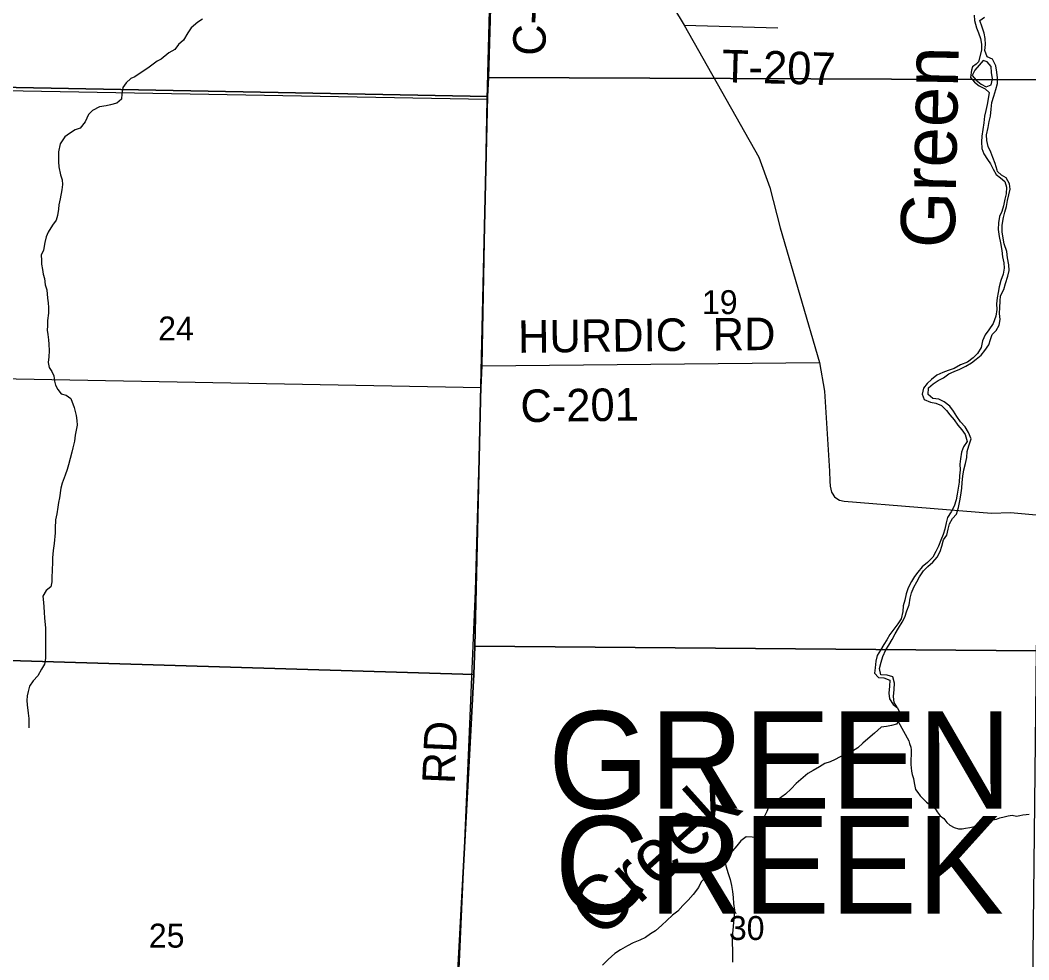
# Model space of a CAD drawing. Extents: x 0 to 34, y 0 to 22.
# Drawn here: x 25.169 to 26.932, y 15.382 to 17.024 of the extents above; entities that cross this region are included whole.
import ezdxf

# ---------------------------------------------------------------- set-up
doc = ezdxf.new("R2010")
doc.units = 0
for name, color, linetype in [('GM_X_County_Road', 7, 'Continuous'), ('GM_X_County_Road_Text', 7, 'Continuous'), ('GM_X_Minor_River', 7, 'Continuous'), ('GM_X_Minor_River_Text', 7, 'Continuous'), ('GM_X_Section', 7, 'Continuous'), ('GM_X_Section_Text', 7, 'Continuous'), ('GM_X_Township_Road', 7, 'Continuous'), ('GM_X_Township_Road_Text', 7, 'Continuous'), ('GM_X_Township_Text', 7, 'Continuous')]:
    doc.layers.add(name, color=color, linetype=linetype)

msp = doc.modelspace()

# ---------------------------------------------------------------- linework, layer by layer
at = {"layer": 'GM_X_County_Road'}
for p, q in [((25.9854, 16.8861), (26.0016, 17.5418)), ((25.9763, 16.4198), (25.9854, 16.8861)), ((25.9746, 16.3822), (25.9763, 16.4198)), ((25.9763, 16.4198), (26.566, 16.4258))]:
    msp.add_line(p, q, dxfattribs=at)
for points in [[(26.0883, 17.4156), (26.3294, 17.015), (26.4602, 16.7846), (26.4794, 16.7319), (26.4973, 16.6609), (26.566, 16.4258)], [(26.566, 16.4258), (26.5747, 16.3759), (26.5835, 16.236), (26.5843, 16.2185), (26.585, 16.2101), (26.5874, 16.1995), (26.5882, 16.1976), (26.5926, 16.191), (26.5963, 16.1882), (26.6013, 16.1852), (26.6092, 16.1839), (26.867, 16.1627), (26.9001, 16.1639), (26.9576, 16.1588)], [(24.007, 16.4066), (24.2617, 16.4112), (24.9115, 16.4019), (25.9746, 16.3822)], [(25.9196, 14.987), (25.9448, 15.5625), (25.9647, 16.0268), (25.9746, 16.3822)]]:
    msp.add_lwpolyline(points, dxfattribs=at)
at = {"layer": 'GM_X_Minor_River'}
for points in [[(26.8367, 17.0328), (26.8372, 17.0233), (26.8403, 17.0106), (26.8442, 17.0018), (26.8474, 16.9922), (26.8494, 16.9823), (26.8494, 16.9713), (26.844, 16.9513), (26.8397, 16.9473), (26.8335, 16.9425), (26.8318, 16.9368), (26.8299, 16.9236), (26.8369, 16.9158), (26.8455, 16.9095), (26.8556, 16.9043), (26.8626, 16.8976), (26.8612, 16.8863), (26.859, 16.8765), (26.8568, 16.8663), (26.8547, 16.8561), (26.8532, 16.8444), (26.8518, 16.833), (26.8499, 16.8213), (26.8493, 16.8114), (26.8497, 16.7997), (26.8536, 16.7904), (26.8598, 16.7804), (26.8653, 16.7727), (26.8696, 16.7634), (26.875, 16.7545), (26.8825, 16.7486)], [(25.4875, 17.026), (25.4798, 17.0204), (25.4679, 17.0103), (25.4621, 17.0016), (25.4548, 16.9892), (25.4456, 16.9813), (25.4394, 16.973), (25.4287, 16.9671), (25.4157, 16.9558), (25.4085, 16.9521), (25.3943, 16.9416), (25.3871, 16.9364), (25.3786, 16.9312), (25.3695, 16.9252), (25.3622, 16.9222), (25.3542, 16.9147), (25.3484, 16.9065), (25.3468, 16.8951), (25.3459, 16.886), (25.3378, 16.8792), (25.3272, 16.8759), (25.3192, 16.8745), (25.3078, 16.8723), (25.2956, 16.8664), (25.2887, 16.8593), (25.2829, 16.8464), (25.274, 16.8355), (25.2652, 16.8326), (25.2553, 16.8262), (25.2469, 16.8199), (25.2392, 16.8082), (25.236, 16.7938), (25.2358, 16.7767), (25.2368, 16.7676), (25.2397, 16.7535), (25.2426, 16.7451), (25.2433, 16.7368), (25.242, 16.7277), (25.2388, 16.7118), (25.2364, 16.7012), (25.236, 16.6936), (25.234, 16.683), (25.232, 16.6743), (25.2254, 16.666), (25.2181, 16.6539), (25.2142, 16.6456), (25.2122, 16.6354), (25.2097, 16.6221), (25.2059, 16.6134), (25.2061, 16.6047), (25.2064, 16.5975), (25.2082, 16.5884), (25.2093, 16.5804), (25.2115, 16.5728), (25.2128, 16.5617), (25.2154, 16.5526), (25.2168, 16.5385), (25.2182, 16.5302), (25.2188, 16.5218), (25.2184, 16.5123), (25.2171, 16.4991), (25.217, 16.4899), (25.2165, 16.4824), (25.2176, 16.4748), (25.2186, 16.4653), (25.2193, 16.4577), (25.2199, 16.4463), (25.219, 16.436), (25.2181, 16.4262), (25.2196, 16.4174), (25.2244, 16.4102), (25.2277, 16.4029), (25.2291, 16.3934), (25.2306, 16.3862), (25.2347, 16.3785), (25.2406, 16.3709), (25.2497, 16.3689), (25.2576, 16.3631), (25.2635, 16.3475), (25.2668, 16.3334), (25.2678, 16.3247), (25.2685, 16.3167), (25.2652, 16.2989), (25.264, 16.2883), (25.2608, 16.2769), (25.2592, 16.2693), (25.2537, 16.2474), (25.2513, 16.2387), (25.2474, 16.2288), (25.2423, 16.2152), (25.2403, 16.2061), (25.2378, 16.1895), (25.2362, 16.1811)], [(26.8768, 16.7621), (26.8733, 16.7736), (26.869, 16.7839), (26.8655, 16.7935), (26.8608, 16.8035), (26.8588, 16.8138), (26.858, 16.8237), (26.8609, 16.8362), (26.8627, 16.8468), (26.8649, 16.8562), (26.8664, 16.8687), (26.8674, 16.88), (26.8708, 16.891), (26.8745, 16.9026), (26.8774, 16.9132), (26.877, 16.9234), (26.8761, 16.9333), (26.8745, 16.944), (26.8684, 16.956), (26.859, 16.96), (26.8551, 16.9707), (26.8562, 16.9813), (26.8557, 16.992), (26.8537, 17.0015), (26.8502, 17.0119), (26.8463, 17.0234), (26.8544, 17.0292)], [(26.852, 16.9534), (26.8453, 16.9456), (26.8379, 16.9367), (26.8331, 16.9273), (26.8397, 16.9192), (26.849, 16.9121), (26.8572, 16.9073), (26.8664, 16.9108), (26.8686, 16.9214)], [(26.8686, 16.9214), (26.867, 16.9328), (26.8661, 16.9431), (26.8591, 16.9509), (26.852, 16.9534)], [(26.8825, 16.7486), (26.8899, 16.742), (26.893, 16.7324), (26.8923, 16.7207), (26.8898, 16.7112), (26.8876, 16.6999), (26.8847, 16.6897), (26.881, 16.6807), (26.8788, 16.6701), (26.8785, 16.658), (26.8804, 16.6462), (26.8824, 16.6351), (26.8851, 16.6214), (26.8863, 16.6107), (26.8883, 16.6), (26.8892, 16.5905), (26.8874, 16.5803), (26.8833, 16.569), (26.8803, 16.5581), (26.8782, 16.5483), (26.8764, 16.5388), (26.8757, 16.5282), (26.8759, 16.5183), (26.8744, 16.5066), (26.8695, 16.4938), (26.8624, 16.483), (26.8557, 16.4745), (26.8509, 16.464), (26.8487, 16.4523), (26.8423, 16.4418), (26.8349, 16.434), (26.8248, 16.4267), (26.8126, 16.4217), (26.8014, 16.4152), (26.7911, 16.4121), (26.7815, 16.4085), (26.7715, 16.4035), (26.7622, 16.3965), (26.7541, 16.3892), (26.7478, 16.381), (26.7456, 16.3704), (26.7491, 16.3612), (26.76, 16.3564), (26.7694, 16.355), (26.7796, 16.3509), (26.7884, 16.3423), (26.7939, 16.3345), (26.8016, 16.326), (26.8082, 16.3163), (26.8152, 16.3081), (26.8207, 16.3004), (26.8245, 16.2881), (26.8178, 16.2785), (26.8145, 16.2694), (26.8127, 16.2577), (26.8113, 16.2483), (26.8118, 16.2384), (26.8111, 16.2278), (26.8104, 16.2168), (26.8083, 16.2062), (26.8068, 16.196), (26.8051, 16.1862), (26.8013, 16.1752), (26.7961, 16.1651), (26.7898, 16.1554), (26.7877, 16.146), (26.7855, 16.1347), (26.7822, 16.1256), (26.7785, 16.1155), (26.7744, 16.105), (26.7696, 16.0956), (26.7644, 16.0859), (26.7551, 16.0767), (26.7458, 16.0689), (26.7379, 16.0597), (26.732, 16.0518), (26.7272, 16.0432), (26.7213, 16.0324), (26.7179, 16.0219), (26.7154, 16.0109), (26.7124, 16.0007), (26.7118, 15.9909), (26.7088, 15.9781), (26.7033, 15.9695), (26.6958, 15.9602), (26.6891, 15.9505), (26.6839, 15.9412), (26.6784, 15.933), (26.6728, 15.9232), (26.6669, 15.9139), (26.6647, 15.9041), (26.6633, 15.8927), (26.6622, 15.8829), (26.6692, 15.8755), (26.6787, 15.8752), (26.6892, 15.8711), (26.6886, 15.8605), (26.6871, 15.848), (26.6887, 15.8385), (26.6949, 15.8285), (26.7023, 15.8226)], [(26.7023, 15.8226), (26.6965, 15.8322), (26.6953, 15.8425), (26.6967, 15.8546), (26.697, 15.8656), (26.6943, 15.8767), (26.6845, 15.8796), (26.6732, 15.8803), (26.6708, 15.8914), (26.6738, 15.9023), (26.6771, 15.9125), (26.6819, 15.9237), (26.6871, 15.9323), (26.693, 15.942), (26.6986, 15.9518), (26.7042, 15.9619), (26.7109, 15.9723), (26.7153, 15.9809), (26.719, 15.9918), (26.7227, 16.0024), (26.7249, 16.0141), (26.7271, 16.0235), (26.7308, 16.0333), (26.736, 16.043), (26.7411, 16.0516), (26.7478, 16.0617), (26.7556, 16.0694), (26.7642, 16.0772), (26.772, 16.0861), (26.7772, 16.0958), (26.7797, 16.1052), (26.7827, 16.1161), (26.789, 16.1243), (26.7908, 16.1345), (26.7933, 16.1439), (26.7985, 16.1533), (26.8055, 16.1611), (26.8089, 16.1728), (26.8114, 16.1841), (26.8132, 16.1939), (26.8147, 16.2064), (26.8153, 16.2162), (26.8168, 16.2276), (26.8186, 16.2386), (26.8212, 16.2495), (26.8234, 16.2601), (26.824, 16.2703), (26.8273, 16.2805), (26.8311, 16.2925), (26.8264, 16.3037), (26.8206, 16.3133), (26.8125, 16.3223), (26.8063, 16.3315), (26.8001, 16.3408), (26.7939, 16.3497), (26.7843, 16.3572), (26.7749, 16.3616), (26.764, 16.3631), (26.7562, 16.3698), (26.7565, 16.3815), (26.7646, 16.3885), (26.7735, 16.3947), (26.7828, 16.3994), (26.7924, 16.406), (26.8016, 16.4099), (26.8112, 16.4142), (26.822, 16.4196), (26.8316, 16.4254), (26.8398, 16.4316), (26.8487, 16.439), (26.855, 16.4468), (26.862, 16.4565), (26.8653, 16.4659), (26.8682, 16.4749), (26.8752, 16.4819), (26.88, 16.4909), (26.8818, 16.5011), (26.881, 16.5114), (26.8813, 16.522), (26.8819, 16.533), (26.8826, 16.5425), (26.8886, 16.5533), (26.8915, 16.5642), (26.8956, 16.577), (26.8978, 16.5865), (26.8969, 16.5967), (26.8946, 16.609), (26.8934, 16.62), (26.8892, 16.6334), (26.8872, 16.6433), (26.8856, 16.6544), (26.8852, 16.6658), (26.8878, 16.679), (26.8903, 16.6884), (26.8932, 16.6986), (26.8947, 16.7092), (26.8972, 16.7186), (26.8994, 16.7288), (26.8985, 16.7383), (26.8927, 16.7484), (26.8845, 16.7531)], [(26.8845, 16.7531), (26.8775, 16.7598), (26.8768, 16.7621)], [(25.2362, 16.1811), (25.235, 16.1732), (25.233, 16.1618), (25.2309, 16.1512), (25.2304, 16.1364), (25.2303, 16.1284), (25.2282, 16.1095), (25.2269, 16.0977), (25.2256, 16.0848), (25.2256, 16.0776), (25.225, 16.0628), (25.2241, 16.0507), (25.2244, 16.0427), (25.2228, 16.034), (25.2147, 16.0276), (25.2089, 16.0174), (25.2096, 16.0064), (25.2106, 15.9992), (25.2109, 15.9893), (25.2115, 15.9798), (25.2132, 15.962), (25.2135, 15.9521), (25.2131, 15.916), (25.2134, 15.9088), (25.2114, 15.899), (25.2064, 15.8899), (25.1998, 15.8786), (25.1917, 15.87), (25.1855, 15.8605), (25.1831, 15.8511), (25.1812, 15.8435), (25.1807, 15.8355), (25.1814, 15.8276), (25.1831, 15.8135), (25.1841, 15.804), (25.1839, 15.7877)], [(26.7023, 15.8226), (26.7063, 15.8137), (26.7044, 15.8016), (26.7039, 15.799), (26.7005, 15.7943)], [(26.7039, 15.799), (26.7222, 15.765), (26.7237, 15.7601), (26.7255, 15.754), (26.7262, 15.7494), (26.7259, 15.7236), (26.7262, 15.7179), (26.7269, 15.7118), (26.7284, 15.7061), (26.7302, 15.6989), (26.7316, 15.6913), (26.7327, 15.6859), (26.7341, 15.6802), (26.7379, 15.6749), (26.7423, 15.6691), (26.7476, 15.6634), (26.7532, 15.658), (26.7577, 15.6545), (26.7626, 15.6514), (26.7683, 15.6468), (26.772, 15.6411), (26.7772, 15.6338), (26.7832, 15.6292), (26.7885, 15.6223), (26.7941, 15.6177), (26.8013, 15.6138), (26.8092, 15.6115), (26.8156, 15.611), (26.8214, 15.6125), (26.829, 15.6135), (26.8373, 15.6153), (26.8442, 15.6172), (26.8495, 15.6198), (26.8548, 15.622), (26.8602, 15.6234), (26.8686, 15.6271), (26.8758, 15.6282), (26.8815, 15.6304), (26.8887, 15.6322), (26.8959, 15.6337), (26.9028, 15.6348), (26.9104, 15.6335), (26.9164, 15.6346), (26.9218, 15.6357), (26.9271, 15.6364), (26.9328, 15.6371)], [(26.7005, 15.7943), (26.6918, 15.7919), (26.683, 15.7901), (26.6739, 15.7887), (26.662, 15.7786), (26.6509, 15.7684), (26.6417, 15.7606), (26.6329, 15.7527), (26.6237, 15.7471), (26.615, 15.7442), (26.5936, 15.7322), (26.5848, 15.7282), (26.5753, 15.7252), (26.5662, 15.7196), (26.5551, 15.7129), (26.5455, 15.7077), (26.5256, 15.6905), (26.5164, 15.6811), (26.5068, 15.6717), (26.4938, 15.6627), (26.4851, 15.659), (26.4777, 15.65), (26.4739, 15.6413), (26.4696, 15.6322), (26.4672, 15.622), (26.467, 15.6023), (26.4574, 15.5955), (26.4487, 15.5968), (26.4381, 15.5973), (26.4289, 15.5905), (26.4216, 15.5815), (26.4139, 15.5725), (26.4058, 15.5623), (26.3966, 15.5552), (26.3859, 15.5473), (26.376, 15.5383), (26.369, 15.5293), (26.3594, 15.5184), (26.3548, 15.5089), (26.3451, 15.4965), (26.3367, 15.4867), (26.3275, 15.4774), (26.3183, 15.4676), (26.3091, 15.4605), (26.2995, 15.4511), (26.2903, 15.4432), (26.2796, 15.4331), (26.2708, 15.4279), (26.262, 15.4215), (26.2521, 15.4167), (26.2406, 15.4119), (26.2303, 15.4067), (26.2185, 15.4), (26.2085, 15.3932), (26.1967, 15.3827), (26.1871, 15.3733)], [(26.4027, 15.5599), (26.4004, 15.5559), (26.4026, 15.5468), (26.4066, 15.5331), (26.4099, 15.5228), (26.4121, 15.5121), (26.4139, 15.5019), (26.4152, 15.4912), (26.4159, 15.4806), (26.4173, 15.4692), (26.4172, 15.4604), (26.4159, 15.4476), (26.4146, 15.4343), (26.4137, 15.4244), (26.4136, 15.4108), (26.4138, 15.4001), (26.4141, 15.3891), (26.414, 15.3781)]]:
    msp.add_lwpolyline(points, dxfattribs=at)
at = {"layer": 'GM_X_Section'}
for points in [[(26.984, 17.9172), (26.974, 16.9197), (25.9875, 16.9239), (26.0158, 17.891), (26.0171, 17.9156)], [(26.0158, 17.891), (25.9875, 16.9239), (25.9861, 16.8906), (24.9171, 16.9109), (24.9267, 17.9117)], [(25.9861, 16.8906), (25.9635, 15.9304), (25.9617, 15.8807), (24.8984, 15.9127), (24.9171, 16.9109)], [(26.974, 16.9197), (26.945, 15.9224), (25.9635, 15.9304), (25.9861, 16.8906), (25.9875, 16.9239)], [(26.945, 15.9224), (26.9342, 14.9655), (25.9137, 14.9847), (25.9617, 15.8807), (25.9635, 15.9304)], [(25.9617, 15.8807), (25.9137, 14.9847), (25.9129, 14.9756), (24.9245, 14.9768), (24.9186, 15.4351), (24.894, 15.7536), (24.8984, 15.9127)]]:
    msp.add_lwpolyline(points, close=True, dxfattribs=at)
at = {"layer": 'GM_X_Township_Road'}
msp.add_line((26.3294, 17.015), (26.4934, 17.0105), dxfattribs=at)
msp.add_lwpolyline([(24.1604, 16.9066), (24.9139, 16.9052), (25.9854, 16.8861)], dxfattribs=at)

# ---------------------------------------------------------------- texts
at = {"layer": 'GM_X_County_Road_Text'}
for s, rotation, p in [('C-198', 88.6237, (26.0869, 16.9613)), ('HURDIC', 0.7187, (26.0396, 16.4427)), ('RD', 0.4936, (26.3797, 16.4468)), ('C-201', 0.8264, (26.0438, 16.3216)), ('RD', 87.5314, (25.9284, 15.6888))]:
    msp.add_text(s, height=0.05682, rotation=rotation, dxfattribs=at).set_placement(p)
at = {"layer": 'GM_X_Minor_River_Text'}
for s, height, rotation, p in [('Green', 0.09475, 88.8302, (26.8023, 16.6251)), ('Creek', 0.09474, 41.9879, (26.1821, 15.4163))]:
    msp.add_text(s, height=height, rotation=rotation, dxfattribs=at).set_placement(p)
at = {"layer": 'GM_X_Section_Text'}
for s, p in [('19', (26.3607, 16.5104)), ('24', (25.4103, 16.4644)), ('25', (25.394, 15.4037)), ('30', (26.4078, 15.417))]:
    msp.add_text(s, height=0.04186, rotation=0, dxfattribs=at).set_placement(p)
at = {"layer": 'GM_X_Township_Road_Text'}
msp.add_text('T-207', height=0.05682, rotation=358.4309, dxfattribs=at).set_placement((26.3951, 16.9157))
at = {"layer": 'GM_X_Township_Text'}
for s, p in [('GREEN', (26.0918, 15.6463)), ('CREEK', (26.1031, 15.4629))]:
    msp.add_text(s, height=0.17045, rotation=0, dxfattribs=at).set_placement(p)

doc.saveas('drawing.dxf')
